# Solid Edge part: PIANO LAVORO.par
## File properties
Subject: PIANO LAVORO
Author: f_grande
Template: Normal.par
Last saved by: f_grande
Revision: 6
Application: Solid Edge
Material: MDF
Stile della faccia: Marroncino
Coef. of Thermal Exp: 0.0
Thermal Conductivity: 0.0
Specific Heat: 0.0
Modulus of Elasticity: 0.0
Poisson's Ratio: 0.0
Yield Stress: 0.0
Ultimate Stress: 0.0
Elongation: 0.0
Tipo di contenuto documento: 0
Densità: 750,000 kg/m^3
Precisione: 0,99
Document Number: KR0115
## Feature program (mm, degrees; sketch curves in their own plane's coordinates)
sketch for "unnamed Protrusion 1" plane through (0, 0, 0) normal (0, 0, 1) x-axis (1, 0, 0)
  line (-55.48, 39.0414) -> (994.52, 39.0414)
  line (994.52, 39.0414) -> (994.52, -645.9586)
  line (994.52, -645.9586) -> (-55.48, -645.9586)
  line (-55.48, -645.9586) -> (-55.48, 39.0414)
  dimension (linear) = 55.48
  dimension (linear) = 55.48
extrude "unnamed Protrusion 1" add finite 19 along +normal
sketch for "Foro_1" plane through (469.52, -303.4586, 19) normal (0, 0, 1) x-axis (1, 0, 0)
  hole centre (-485, 308.75) bore radius 4
hole "Foro_1" diameter 8 through  CounterSinkAngle = 82 deg
pattern "unnamed Pattern 1" of "Foro_1"
pattern "unnamed Pattern 2"
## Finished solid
Body 1: solid body, 70 faces, 108 edges, 8 vertices.
  Faces by surface: cone 32, cylinder 32, plane 6
  Edges by curve: circle 96, line 12
Bounding box of the edges (mm): 1050.000 x 685.000 x 19.000, from (-55.48, -645.9586, 0) to (994.52, 39.0414, 19).
Cylindrical faces by radius (mm): R4 x32
Conical faces (half-angle, radius in mm at the cone's reference point): 41 deg R7.5 x32
Planar faces by outward normal: +x 1, +y 1, +z 1, -x 1, -y 1, -z 1
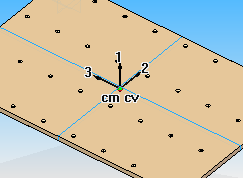
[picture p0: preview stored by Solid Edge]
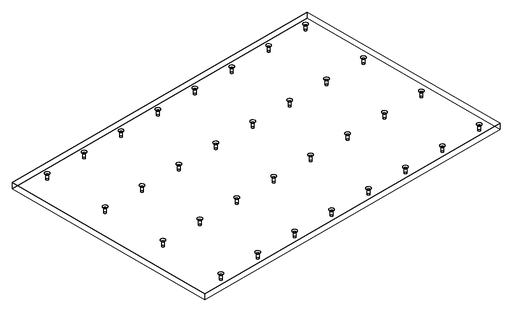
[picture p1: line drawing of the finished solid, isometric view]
